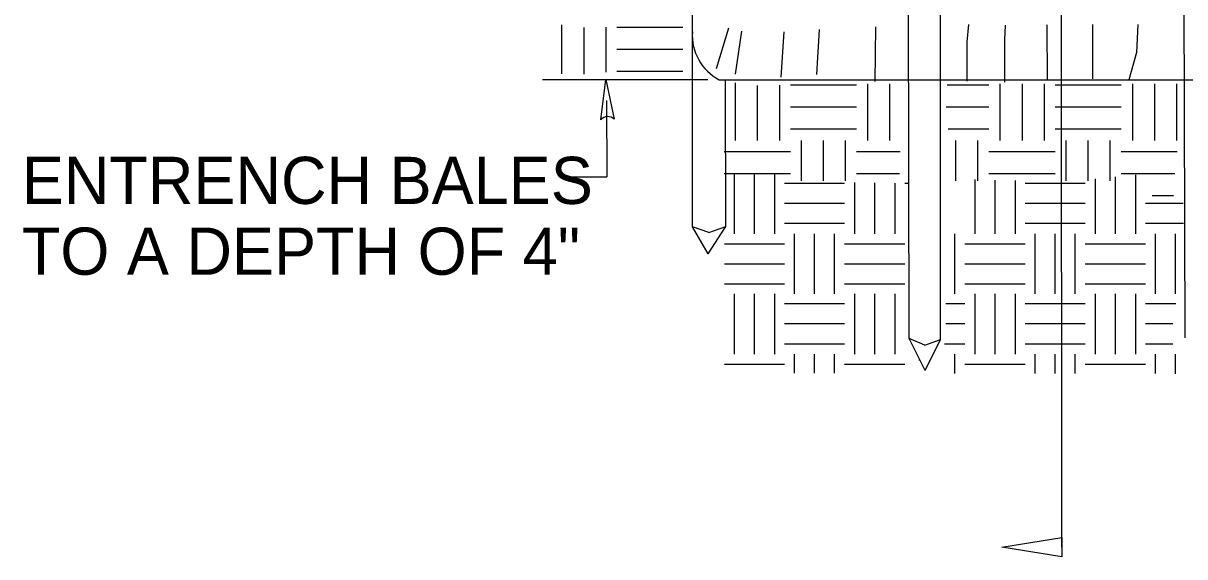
# Model space of a CAD drawing. Extents: x 0 to 2.83, y -0.06 to 1.83.
# Drawn here: x 0.5312 to 0.7467, y 0.8602 to 0.9591 of the extents above; entities that cross this region are included whole.
import ezdxf

# ---------------------------------------------------------------- set-up
doc = ezdxf.new("R2010")
doc.units = 0
for name, color, linetype in [('Edge_of_Truck_Apron', 7, 'Continuous'), ('Existing Soil', 7, 'Continuous'), ('Haybales', 7, 'Continuous'), ('Longitudinal Joint', 7, 'Continuous'), ('Wood Stakes', 7, 'Continuous')]:
    doc.layers.add(name, color=color, linetype=linetype)

msp = doc.modelspace()

# ---------------------------------------------------------------- linework, layer by layer
at = {"layer": 'Edge_of_Truck_Apron'}
for p, q in [((0.7239419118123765, 0.8619778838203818), (0.7236669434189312, 1.1529230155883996)), ((0.6383749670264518, 0.9412304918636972), (0.6392960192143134, 0.9487215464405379)), ((0.6383749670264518, 0.9412304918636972), (0.6392960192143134, 0.9487215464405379)), ((0.6392960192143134, 0.9487215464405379), (0.6408542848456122, 0.941336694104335)), ((0.6392960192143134, 0.9487215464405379), (0.6408542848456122, 0.941336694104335)), ((0.639452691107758, 0.9448351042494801), (0.6395039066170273, 0.9306306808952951)), ((0.6308424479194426, 0.9306402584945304), (0.6395039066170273, 0.9306306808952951))]:
    msp.add_line(p, q, dxfattribs=at)
msp.add_lwpolyline([(0.7239455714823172, 0.8601893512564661), (0.7127635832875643, 0.8619550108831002), (0.7239382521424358, 0.8637664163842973)], close=True, dxfattribs=at)
msp.add_arc((0.6396640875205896, 0.9401288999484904), 0.0016956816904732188, 45.42043531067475, 139.48512104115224, dxfattribs=at)
msp.add_arc((0.6396640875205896, 0.9401288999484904), 0.0016956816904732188, 45.42043531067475, 139.48512104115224, dxfattribs=at)
at = {"layer": 'Existing Soil'}
for p, q in [((0.6310945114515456, 0.9588487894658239), (0.6310945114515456, 0.949758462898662)), ((0.6351891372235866, 0.9583418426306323), (0.6351891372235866, 0.9497080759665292)), ((0.6392837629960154, 0.9584000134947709), (0.6392837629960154, 0.9500607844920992)), ((0.6536149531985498, 0.9583877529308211), (0.6413310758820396, 0.9583877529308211)), ((0.6536149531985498, 0.954293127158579), (0.6413310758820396, 0.954293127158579)), ((0.6536149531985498, 0.9501985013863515), (0.6413310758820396, 0.9501985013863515)), ((0.6633135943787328, 0.9481212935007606), (0.6633135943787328, 0.9374236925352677)), ((0.6633135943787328, 0.9481212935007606), (0.6633135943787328, 0.9374236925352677)), ((0.6674082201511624, 0.9476143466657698), (0.6674082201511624, 0.9374236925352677)), ((0.6674082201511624, 0.9476143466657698), (0.6674082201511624, 0.9374236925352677)), ((0.671502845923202, 0.9476725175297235), (0.671502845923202, 0.9374236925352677)), ((0.671502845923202, 0.9476725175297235), (0.671502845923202, 0.9374236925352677)), ((0.6858340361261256, 0.9476602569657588), (0.6735501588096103, 0.9476602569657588)), ((0.6858340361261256, 0.9476602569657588), (0.6735501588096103, 0.9476602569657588)), ((0.6878813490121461, 0.9478773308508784), (0.6878813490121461, 0.9374236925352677)), ((0.6878813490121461, 0.9478773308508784), (0.6878813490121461, 0.9374236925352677)), ((0.6919759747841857, 0.9478773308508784), (0.6919759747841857, 0.9374236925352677)), ((0.6919759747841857, 0.9478773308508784), (0.6919759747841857, 0.9374236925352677)), ((0.7104017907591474, 0.9476602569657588), (0.702675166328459, 0.9476602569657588)), ((0.7104017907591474, 0.9476602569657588), (0.702675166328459, 0.9476602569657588)), ((0.7124491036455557, 0.9478773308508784), (0.7124491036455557, 0.9374236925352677)), ((0.7124491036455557, 0.9478773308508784), (0.7124491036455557, 0.9374236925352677)), ((0.7165437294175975, 0.9478773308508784), (0.7165437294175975, 0.9374236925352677)), ((0.7165437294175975, 0.9478773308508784), (0.7165437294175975, 0.9374236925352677)), ((0.7206383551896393, 0.9478773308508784), (0.7206383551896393, 0.9374236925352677)), ((0.7206383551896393, 0.9478773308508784), (0.7206383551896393, 0.9374236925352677)), ((0.7349695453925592, 0.9476602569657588), (0.7226856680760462, 0.9476602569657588)), ((0.7349695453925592, 0.9476602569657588), (0.7226856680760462, 0.9476602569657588)), ((0.7370168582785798, 0.9478773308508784), (0.7370168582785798, 0.9374236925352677)), ((0.7370168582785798, 0.9478773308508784), (0.7370168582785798, 0.9374236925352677)), ((0.7411114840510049, 0.9478773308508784), (0.7411114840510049, 0.9374236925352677)), ((0.7411114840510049, 0.9478773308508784), (0.7411114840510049, 0.9374236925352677)), ((0.7452061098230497, 0.9478773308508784), (0.7452061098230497, 0.9374236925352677)), ((0.7452061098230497, 0.9478773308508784), (0.7452061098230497, 0.9374236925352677)), ((0.6858340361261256, 0.9435656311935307), (0.6735501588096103, 0.9435656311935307)), ((0.6858340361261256, 0.9435656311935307), (0.6735501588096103, 0.9435656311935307)), ((0.7104017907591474, 0.9435656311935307), (0.7024463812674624, 0.9435656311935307)), ((0.7104017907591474, 0.9435656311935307), (0.7024463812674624, 0.9435656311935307)), ((0.7349695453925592, 0.9435656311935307), (0.7226856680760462, 0.9435656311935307)), ((0.7349695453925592, 0.9435656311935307), (0.7226856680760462, 0.9435656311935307)), ((0.6858340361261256, 0.9394710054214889), (0.6735501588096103, 0.9394710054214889)), ((0.6858340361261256, 0.9394710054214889), (0.6735501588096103, 0.9394710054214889)), ((0.7104017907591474, 0.9394710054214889), (0.7028276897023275, 0.9394710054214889)), ((0.7104017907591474, 0.9394710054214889), (0.7028276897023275, 0.9394710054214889)), ((0.7349695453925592, 0.9394710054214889), (0.7226856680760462, 0.9394710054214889)), ((0.7349695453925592, 0.9394710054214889), (0.7226856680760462, 0.9394710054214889)), ((0.6755974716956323, 0.9299010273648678), (0.6755974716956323, 0.9374236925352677)), ((0.6755974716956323, 0.9299010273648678), (0.6755974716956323, 0.9374236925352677)), ((0.6796920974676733, 0.9299010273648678), (0.6796920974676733, 0.9374236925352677)), ((0.6796920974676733, 0.9299010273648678), (0.6796920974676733, 0.9374236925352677)), ((0.6837867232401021, 0.9299010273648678), (0.6837867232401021, 0.9374236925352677)), ((0.6837867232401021, 0.9299010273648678), (0.6837867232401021, 0.9374236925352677)), ((0.704259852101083, 0.9299010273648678), (0.704259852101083, 0.9374236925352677)), ((0.704259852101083, 0.9299010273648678), (0.704259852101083, 0.9374236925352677)), ((0.708354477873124, 0.9299010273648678), (0.708354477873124, 0.9374236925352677)), ((0.708354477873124, 0.9299010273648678), (0.708354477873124, 0.9374236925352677)), ((0.7247329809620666, 0.9299010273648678), (0.7247329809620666, 0.9374236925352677)), ((0.7247329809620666, 0.9299010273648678), (0.7247329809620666, 0.9374236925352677)), ((0.7288276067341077, 0.9299010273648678), (0.7288276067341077, 0.9374236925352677)), ((0.7288276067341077, 0.9299010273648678), (0.7288276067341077, 0.9374236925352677)), ((0.7329222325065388, 0.9299010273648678), (0.7329222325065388, 0.9374236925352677)), ((0.7329222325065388, 0.9299010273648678), (0.7329222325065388, 0.9374236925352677)), ((0.6858340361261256, 0.935376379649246), (0.6939050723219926, 0.935376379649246)), ((0.6858340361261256, 0.935376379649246), (0.6939050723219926, 0.935376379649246)), ((0.7104017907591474, 0.935376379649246), (0.7226856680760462, 0.935376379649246)), ((0.7104017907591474, 0.935376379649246), (0.7226856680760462, 0.935376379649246)), ((0.7349695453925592, 0.935376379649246), (0.7453067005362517, 0.935376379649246)), ((0.7349695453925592, 0.935376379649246), (0.7453067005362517, 0.935376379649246)), ((0.6858340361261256, 0.931281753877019), (0.6938288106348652, 0.931281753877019)), ((0.6858340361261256, 0.931281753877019), (0.6938288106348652, 0.931281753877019)), ((0.7104017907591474, 0.931281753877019), (0.7226856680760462, 0.931281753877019)), ((0.7104017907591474, 0.931281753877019), (0.7226856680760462, 0.931281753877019)), ((0.7349695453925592, 0.931281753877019), (0.7448796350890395, 0.931281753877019)), ((0.7349695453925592, 0.931281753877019), (0.7448796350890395, 0.931281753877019)), ((0.6631274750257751, 0.9312783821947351), (0.6631274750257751, 0.9201145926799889)), ((0.6631274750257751, 0.9312783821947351), (0.6631274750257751, 0.9201145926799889)), ((0.6668498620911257, 0.9312716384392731), (0.6668498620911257, 0.9201145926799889)), ((0.6668498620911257, 0.9312716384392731), (0.6668498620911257, 0.9201145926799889)), ((0.6705722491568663, 0.9312648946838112), (0.6705722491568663, 0.9201145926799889)), ((0.6705722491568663, 0.9312648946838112), (0.6705722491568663, 0.9201145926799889)), ((0.6836006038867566, 0.9294205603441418), (0.6724334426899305, 0.9294205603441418)), ((0.6836006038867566, 0.9294205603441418), (0.6724334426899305, 0.9294205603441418)), ((0.685461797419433, 0.9296342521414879), (0.685461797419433, 0.9201145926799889)), ((0.685461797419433, 0.9296342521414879), (0.685461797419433, 0.9201145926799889)), ((0.6891841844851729, 0.9295539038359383), (0.6891841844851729, 0.9201145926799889)), ((0.6891841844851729, 0.9295539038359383), (0.6891841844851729, 0.9201145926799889)), ((0.6929065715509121, 0.9294735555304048), (0.6929065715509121, 0.9201145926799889)), ((0.6929065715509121, 0.9294735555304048), (0.6929065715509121, 0.9201145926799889)), ((0.6953617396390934, 0.9294205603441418), (0.6947677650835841, 0.9294205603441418)), ((0.6953617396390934, 0.9294205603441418), (0.6947677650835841, 0.9294205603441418)), ((0.707796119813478, 0.9301386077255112), (0.707796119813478, 0.9201145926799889)), ((0.707796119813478, 0.9301386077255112), (0.707796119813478, 0.9201145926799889)), ((0.7115185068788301, 0.9300602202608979), (0.7115185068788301, 0.9201145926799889)), ((0.7115185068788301, 0.9300602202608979), (0.7115185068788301, 0.9201145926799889)), ((0.71524089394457, 0.9299818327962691), (0.71524089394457, 0.9201145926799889)), ((0.71524089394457, 0.9299818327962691), (0.71524089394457, 0.9201145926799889)), ((0.7282692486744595, 0.9294205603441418), (0.7171020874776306, 0.9294205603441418)), ((0.7282692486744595, 0.9294205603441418), (0.7171020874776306, 0.9294205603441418)), ((0.7301304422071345, 0.930299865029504), (0.7301304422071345, 0.9201145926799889)), ((0.7301304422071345, 0.930299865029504), (0.7301304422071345, 0.9201145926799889)), ((0.7338528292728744, 0.9306669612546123), (0.7338528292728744, 0.9201145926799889)), ((0.7338528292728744, 0.9306669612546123), (0.7338528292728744, 0.9201145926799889)), ((0.7375752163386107, 0.9310340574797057), (0.7375752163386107, 0.9201145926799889)), ((0.7375752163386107, 0.9310340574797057), (0.7375752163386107, 0.9201145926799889)), ((0.7407028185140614, 0.927187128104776), (0.7446355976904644, 0.927187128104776)), ((0.7407028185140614, 0.927187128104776), (0.7446355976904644, 0.927187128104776)), ((0.6836006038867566, 0.9256981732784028), (0.6724334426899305, 0.9256981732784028)), ((0.6836006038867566, 0.9256981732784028), (0.6724334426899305, 0.9256981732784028)), ((0.7282692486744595, 0.9256981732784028), (0.7171020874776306, 0.9256981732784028)), ((0.7282692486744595, 0.9256981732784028), (0.7171020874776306, 0.9256981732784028)), ((0.7464678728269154, 0.9256981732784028), (0.7394364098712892, 0.9256981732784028)), ((0.7464678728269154, 0.9256981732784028), (0.7394364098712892, 0.9256981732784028)), ((0.6836006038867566, 0.9219757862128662), (0.6724334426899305, 0.9219757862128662)), ((0.6836006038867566, 0.9219757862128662), (0.6724334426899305, 0.9219757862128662)), ((0.7282692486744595, 0.9219757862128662), (0.7171020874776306, 0.9219757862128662)), ((0.7282692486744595, 0.9219757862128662), (0.7171020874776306, 0.9219757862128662)), ((0.7465155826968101, 0.9219757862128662), (0.7394364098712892, 0.9219757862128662)), ((0.7465155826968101, 0.9219757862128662), (0.7394364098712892, 0.9219757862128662)), ((0.6742946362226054, 0.9089474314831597), (0.6742946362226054, 0.9201145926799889)), ((0.6742946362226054, 0.9089474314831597), (0.6742946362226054, 0.9201145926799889)), ((0.6780170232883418, 0.9089474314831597), (0.6780170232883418, 0.9201145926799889)), ((0.6780170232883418, 0.9089474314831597), (0.6780170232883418, 0.9201145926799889)), ((0.6817394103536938, 0.9089474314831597), (0.6817394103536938, 0.9201145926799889)), ((0.6817394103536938, 0.9089474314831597), (0.6817394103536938, 0.9201145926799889)), ((0.7040737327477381, 0.9089474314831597), (0.7040737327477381, 0.9201145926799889)), ((0.7040737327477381, 0.9089474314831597), (0.7040737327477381, 0.9201145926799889)), ((0.7189632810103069, 0.9089474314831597), (0.7189632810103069, 0.9201145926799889)), ((0.7189632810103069, 0.9089474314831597), (0.7189632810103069, 0.9201145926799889)), ((0.7226856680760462, 0.9089474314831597), (0.7226856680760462, 0.9201145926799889)), ((0.7226856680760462, 0.9089474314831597), (0.7226856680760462, 0.9201145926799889)), ((0.7264080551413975, 0.9089474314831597), (0.7264080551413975, 0.9201145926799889)), ((0.7264080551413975, 0.9089474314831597), (0.7264080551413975, 0.9201145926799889)), ((0.7412976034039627, 0.9089474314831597), (0.7412976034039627, 0.9201145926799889)), ((0.7412976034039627, 0.9089474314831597), (0.7412976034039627, 0.9201145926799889)), ((0.745019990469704, 0.9089474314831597), (0.745019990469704, 0.9201145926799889)), ((0.745019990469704, 0.9089474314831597), (0.745019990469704, 0.9201145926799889)), ((0.6836006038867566, 0.9182533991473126), (0.6947677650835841, 0.9182533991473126)), ((0.6836006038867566, 0.9182533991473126), (0.6947677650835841, 0.9182533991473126)), ((0.7059349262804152, 0.9182533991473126), (0.7171020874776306, 0.9182533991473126)), ((0.7059349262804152, 0.9182533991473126), (0.7171020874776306, 0.9182533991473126)), ((0.7282692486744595, 0.9182533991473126), (0.7394364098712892, 0.9182533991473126)), ((0.7282692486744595, 0.9182533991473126), (0.7394364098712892, 0.9182533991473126)), ((0.661304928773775, 0.9145310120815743), (0.6724334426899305, 0.9145310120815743)), ((0.661304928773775, 0.9145310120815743), (0.6724334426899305, 0.9145310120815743)), ((0.6836006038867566, 0.9145310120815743), (0.6947677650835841, 0.9145310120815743)), ((0.6836006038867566, 0.9145310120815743), (0.6947677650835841, 0.9145310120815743)), ((0.7059349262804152, 0.9145310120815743), (0.7171020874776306, 0.9145310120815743)), ((0.7059349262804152, 0.9145310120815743), (0.7171020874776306, 0.9145310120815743)), ((0.7282692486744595, 0.9145310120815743), (0.7394364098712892, 0.9145310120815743)), ((0.7282692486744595, 0.9145310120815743), (0.7394364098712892, 0.9145310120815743)), ((0.6613135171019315, 0.9108086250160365), (0.6724334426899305, 0.9108086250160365)), ((0.6613135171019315, 0.9108086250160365), (0.6724334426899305, 0.9108086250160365)), ((0.6836006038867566, 0.9108086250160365), (0.6947677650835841, 0.9108086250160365)), ((0.6836006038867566, 0.9108086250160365), (0.6947677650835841, 0.9108086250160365)), ((0.7059349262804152, 0.9108086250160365), (0.7171020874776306, 0.9108086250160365)), ((0.7059349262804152, 0.9108086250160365), (0.7171020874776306, 0.9108086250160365)), ((0.7282692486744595, 0.9108086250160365), (0.7394364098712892, 0.9108086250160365)), ((0.7282692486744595, 0.9108086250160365), (0.7394364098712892, 0.9108086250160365)), ((0.6631274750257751, 0.9089474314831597), (0.6631274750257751, 0.8977802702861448)), ((0.6631274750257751, 0.9089474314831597), (0.6631274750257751, 0.8977802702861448)), ((0.6668498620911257, 0.9089474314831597), (0.6668498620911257, 0.8977802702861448)), ((0.6668498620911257, 0.9089474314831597), (0.6668498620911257, 0.8977802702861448)), ((0.6705722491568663, 0.9089474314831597), (0.6705722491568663, 0.8977802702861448)), ((0.6705722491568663, 0.9089474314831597), (0.6705722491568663, 0.8977802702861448)), ((0.685461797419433, 0.9089474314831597), (0.685461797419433, 0.8977802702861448)), ((0.685461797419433, 0.9089474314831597), (0.685461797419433, 0.8977802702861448)), ((0.6891841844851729, 0.9089474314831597), (0.6891841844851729, 0.8977802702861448)), ((0.6891841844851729, 0.9089474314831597), (0.6891841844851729, 0.8977802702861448)), ((0.6929065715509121, 0.9089474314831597), (0.6929065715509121, 0.8977802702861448)), ((0.6929065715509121, 0.9089474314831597), (0.6929065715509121, 0.8977802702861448)), ((0.707796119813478, 0.9089474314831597), (0.707796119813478, 0.8977802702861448)), ((0.707796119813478, 0.9089474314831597), (0.707796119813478, 0.8977802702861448)), ((0.7115185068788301, 0.9089474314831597), (0.7115185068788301, 0.8977802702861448)), ((0.7115185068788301, 0.9089474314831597), (0.7115185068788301, 0.8977802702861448)), ((0.71524089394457, 0.9089474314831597), (0.71524089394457, 0.8977802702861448)), ((0.71524089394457, 0.9089474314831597), (0.71524089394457, 0.8977802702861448)), ((0.7301304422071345, 0.9089474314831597), (0.7301304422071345, 0.8977802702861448)), ((0.7301304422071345, 0.9089474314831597), (0.7301304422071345, 0.8977802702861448)), ((0.7338528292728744, 0.9089474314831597), (0.7338528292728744, 0.8977802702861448)), ((0.7338528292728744, 0.9089474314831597), (0.7338528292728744, 0.8977802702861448)), ((0.7375752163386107, 0.9089474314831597), (0.7375752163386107, 0.8977802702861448)), ((0.7375752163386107, 0.9089474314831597), (0.7375752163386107, 0.8977802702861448)), ((0.6836006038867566, 0.9070862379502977), (0.6724334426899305, 0.9070862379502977)), ((0.6836006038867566, 0.9070862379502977), (0.6724334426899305, 0.9070862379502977)), ((0.7059349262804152, 0.9070862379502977), (0.7024157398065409, 0.9070862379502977)), ((0.7059349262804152, 0.9070862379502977), (0.7024157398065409, 0.9070862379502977)), ((0.7282692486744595, 0.9070862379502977), (0.7171020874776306, 0.9070862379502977)), ((0.7282692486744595, 0.9070862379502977), (0.7171020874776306, 0.9070862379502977)), ((0.7451141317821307, 0.9070862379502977), (0.7394364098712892, 0.9070862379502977)), ((0.7451141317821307, 0.9070862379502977), (0.7394364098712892, 0.9070862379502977)), ((0.6836006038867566, 0.9033638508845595), (0.6724334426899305, 0.9033638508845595)), ((0.6836006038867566, 0.9033638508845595), (0.6724334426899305, 0.9033638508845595)), ((0.7059349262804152, 0.9033638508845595), (0.7024157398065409, 0.9033638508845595)), ((0.7059349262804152, 0.9033638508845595), (0.7024157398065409, 0.9033638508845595)), ((0.7282692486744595, 0.9033638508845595), (0.7171020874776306, 0.9033638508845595)), ((0.7282692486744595, 0.9033638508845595), (0.7171020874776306, 0.9033638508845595)), ((0.7445421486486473, 0.9033638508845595), (0.7394364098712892, 0.9033638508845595)), ((0.7445421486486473, 0.9033638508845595), (0.7394364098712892, 0.9033638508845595)), ((0.6836006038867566, 0.8996414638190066), (0.6724334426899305, 0.8996414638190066)), ((0.6836006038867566, 0.8996414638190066), (0.6724334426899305, 0.8996414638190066)), ((0.7059349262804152, 0.8996414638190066), (0.7021774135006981, 0.8996414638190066)), ((0.7059349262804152, 0.8996414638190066), (0.7021774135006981, 0.8996414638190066)), ((0.7282692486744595, 0.8996414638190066), (0.7171020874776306, 0.8996414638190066)), ((0.7282692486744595, 0.8996414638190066), (0.7171020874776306, 0.8996414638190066)), ((0.7445421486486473, 0.8996414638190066), (0.7394364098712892, 0.8996414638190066)), ((0.7445421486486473, 0.8996414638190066), (0.7394364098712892, 0.8996414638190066)), ((0.6742946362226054, 0.8942439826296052), (0.6742946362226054, 0.8977802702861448)), ((0.6742946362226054, 0.8942439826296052), (0.6742946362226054, 0.8977802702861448)), ((0.6780170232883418, 0.8942389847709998), (0.6780170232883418, 0.8977802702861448)), ((0.6780170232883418, 0.8942389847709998), (0.6780170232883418, 0.8977802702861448)), ((0.6817394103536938, 0.8942339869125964), (0.6817394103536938, 0.8977802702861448)), ((0.6817394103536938, 0.8942339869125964), (0.6817394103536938, 0.8977802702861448)), ((0.7040737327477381, 0.8942039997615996), (0.7040737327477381, 0.8977802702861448)), ((0.7040737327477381, 0.8942039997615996), (0.7040737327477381, 0.8977802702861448)), ((0.7189632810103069, 0.8941840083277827), (0.7189632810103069, 0.8977802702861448)), ((0.7189632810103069, 0.8941840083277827), (0.7189632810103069, 0.8977802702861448)), ((0.7226856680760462, 0.8941790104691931), (0.7226856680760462, 0.8977802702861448)), ((0.7226856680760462, 0.8941790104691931), (0.7226856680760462, 0.8977802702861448)), ((0.7264080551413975, 0.8941740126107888), (0.7264080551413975, 0.8977802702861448)), ((0.7264080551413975, 0.8941740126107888), (0.7264080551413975, 0.8977802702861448)), ((0.7412976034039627, 0.8941540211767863), (0.7412976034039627, 0.8977802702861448)), ((0.7412976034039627, 0.8941540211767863), (0.7412976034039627, 0.8977802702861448)), ((0.745019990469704, 0.8941490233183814), (0.745019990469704, 0.8977802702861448)), ((0.745019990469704, 0.8941490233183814), (0.745019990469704, 0.8977802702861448)), ((0.6613478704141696, 0.8959190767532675), (0.6724334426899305, 0.8959190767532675)), ((0.6613478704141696, 0.8959190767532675), (0.6724334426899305, 0.8959190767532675)), ((0.6836006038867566, 0.8959190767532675), (0.6947677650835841, 0.8959190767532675)), ((0.6836006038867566, 0.8959190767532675), (0.6947677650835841, 0.8959190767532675)), ((0.7059349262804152, 0.8959190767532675), (0.7171020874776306, 0.8959190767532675)), ((0.7059349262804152, 0.8959190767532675), (0.7171020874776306, 0.8959190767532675)), ((0.7282692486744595, 0.8959190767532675), (0.7394364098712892, 0.8959190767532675)), ((0.7282692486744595, 0.8959190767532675), (0.7394364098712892, 0.8959190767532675))]:
    msp.add_line(p, q, dxfattribs=at)
at = {"layer": 'Haybales'}
for p, q in [((0.6553708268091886, 0.9575566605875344), (0.6552817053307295, 1.0384090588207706)), ((0.6553708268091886, 0.9575566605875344), (0.6552817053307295, 1.0384090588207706)), ((0.6598220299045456, 0.9507249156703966), (0.6621550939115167, 0.9582975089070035)), ((0.6598220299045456, 0.9507249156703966), (0.6621550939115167, 0.9582975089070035)), ((0.6645069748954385, 0.9576722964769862), (0.6633120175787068, 0.9497036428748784)), ((0.6645069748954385, 0.9576722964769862), (0.6633120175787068, 0.9497036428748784)), ((0.6723050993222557, 0.957539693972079), (0.6717981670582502, 0.9491730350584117)), ((0.6723050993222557, 0.957539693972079), (0.6717981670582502, 0.9491730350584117)), ((0.678899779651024, 0.9579906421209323), (0.6783928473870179, 0.9496239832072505)), ((0.678899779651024, 0.9579906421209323), (0.6783928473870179, 0.9496239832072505)), ((0.6892918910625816, 0.9483563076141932), (0.6894320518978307, 0.9584918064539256)), ((0.6892918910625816, 0.9483563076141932), (0.6894320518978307, 0.9584918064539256)), ((0.7066291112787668, 0.9589142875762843), (0.70628923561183, 0.9556845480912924)), ((0.7066291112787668, 0.9589142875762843), (0.70628923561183, 0.9556845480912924)), ((0.7134197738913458, 0.9587692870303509), (0.7132706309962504, 0.9560093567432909)), ((0.7134197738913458, 0.9587692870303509), (0.7132706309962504, 0.9560093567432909)), ((0.7211472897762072, 0.9588362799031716), (0.7211926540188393, 0.9485982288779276)), ((0.7211472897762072, 0.9588362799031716), (0.7211926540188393, 0.9485982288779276)), ((0.7296317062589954, 0.9589316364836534), (0.7296317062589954, 0.9488270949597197)), ((0.7296317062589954, 0.9589316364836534), (0.7296317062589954, 0.9488270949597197)), ((0.7380093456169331, 0.9589075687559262), (0.737773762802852, 0.9537233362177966)), ((0.7380093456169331, 0.9589075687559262), (0.737773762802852, 0.9537233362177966)), ((0.70628923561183, 0.9556845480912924), (0.70628923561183, 0.9483763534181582)), ((0.70628923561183, 0.9556845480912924), (0.70628923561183, 0.9483763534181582)), ((0.737773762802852, 0.9537233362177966), (0.7363543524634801, 0.9486526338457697)), ((0.737773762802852, 0.9537233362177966), (0.7363543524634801, 0.9486526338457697)), ((0.6603424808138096, 0.948676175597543), (0.8055369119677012, 0.948676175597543)), ((0.6603424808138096, 0.948676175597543), (0.8055369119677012, 0.948676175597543))]:
    msp.add_line(p, q, dxfattribs=at)
msp.add_arc((0.6646313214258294, 0.9569091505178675), 0.009283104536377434, 176.00028812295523, 242.48343833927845, dxfattribs=at)
msp.add_arc((0.6646313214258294, 0.9569091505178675), 0.009283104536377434, 176.00028812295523, 242.48343833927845, dxfattribs=at)
at = {"layer": 'Longitudinal Joint'}
for p, q in [((0.7014009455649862, 0.9006230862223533), (0.7014238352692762, 0.9873487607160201)), ((0.6310945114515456, 0.9588487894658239), (0.6310945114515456, 0.949758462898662)), ((0.6351891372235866, 0.9583418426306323), (0.6351891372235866, 0.9497080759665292)), ((0.6392837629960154, 0.9584000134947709), (0.6392837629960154, 0.9500607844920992)), ((0.6536149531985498, 0.9583877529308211), (0.6413310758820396, 0.9583877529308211)), ((0.6553899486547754, 0.9213868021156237), (0.6553708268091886, 0.9575566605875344)), ((0.7132706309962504, 0.9560093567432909), (0.7132706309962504, 0.9482139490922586)), ((0.7132706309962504, 0.9560093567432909), (0.7132706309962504, 0.9482139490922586)), ((0.6536149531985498, 0.954293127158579), (0.6413310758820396, 0.954293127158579)), ((0.6582508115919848, 0.9486756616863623), (0.6275373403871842, 0.9486681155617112)), ((0.6582508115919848, 0.9486756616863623), (0.6275373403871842, 0.9486681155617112)), ((0.6536149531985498, 0.9501985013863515), (0.6413310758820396, 0.9501985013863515)), ((0.6615679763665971, 0.921443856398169), (0.6614911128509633, 0.9485766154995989)), ((0.639452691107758, 0.9448351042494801), (0.6395039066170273, 0.9306306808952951)), ((0.6612662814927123, 0.935376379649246), (0.6735501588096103, 0.935376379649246)), ((0.6612662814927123, 0.935376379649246), (0.6735501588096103, 0.935376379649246)), ((0.6612662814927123, 0.931281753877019), (0.6735501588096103, 0.931281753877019)), ((0.6612662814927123, 0.931281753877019), (0.6735501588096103, 0.931281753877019)), ((0.6308424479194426, 0.9306402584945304), (0.6395039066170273, 0.9306306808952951)), ((0.6582972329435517, 0.9163564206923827), (0.6553899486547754, 0.9213868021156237)), ((0.6584027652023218, 0.9203492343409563), (0.6553899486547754, 0.9213868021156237)), ((0.6582972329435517, 0.9163564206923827), (0.6615679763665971, 0.921443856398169)), ((0.6584027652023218, 0.9203492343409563), (0.6615679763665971, 0.921443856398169)), ((0.6612963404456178, 0.9182533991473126), (0.6724334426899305, 0.9182533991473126)), ((0.6612963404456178, 0.9182533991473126), (0.6724334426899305, 0.9182533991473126)), ((0.6985393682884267, 0.8947343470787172), (0.695585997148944, 0.9006696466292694)), ((0.6984915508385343, 0.8994140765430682), (0.695585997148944, 0.9006696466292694)), ((0.6984915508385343, 0.8994140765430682), (0.7014075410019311, 0.9005143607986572)), ((0.6985393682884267, 0.8947343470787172), (0.7014075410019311, 0.9005143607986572)), ((0.6975756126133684, 0.8966711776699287), (0.6973910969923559, 0.8966711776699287)), ((0.6975756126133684, 0.8966711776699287), (0.6973910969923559, 0.8966711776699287))]:
    msp.add_line(p, q, dxfattribs=at)
at = {"layer": 'Wood Stakes'}
for p, q in [((0.7014075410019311, 0.9005143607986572), (0.7014238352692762, 0.9873487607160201)), ((0.695585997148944, 0.9006696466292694), (0.6954195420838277, 0.9757475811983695)), ((0.7467912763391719, 0.900822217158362), (0.7466248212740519, 0.9757475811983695)), ((0.6553899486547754, 0.9213868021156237), (0.6553708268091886, 0.9575566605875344)), ((0.6615679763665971, 0.921443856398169), (0.6614911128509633, 0.9485766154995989)), ((0.6582972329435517, 0.9163564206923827), (0.6553899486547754, 0.9213868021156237)), ((0.6584027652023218, 0.9203492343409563), (0.6553899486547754, 0.9213868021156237)), ((0.6582972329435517, 0.9163564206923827), (0.6615679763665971, 0.921443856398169)), ((0.6584027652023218, 0.9203492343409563), (0.6615679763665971, 0.921443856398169)), ((0.6985393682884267, 0.8947343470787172), (0.695585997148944, 0.9006696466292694)), ((0.6984915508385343, 0.8994140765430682), (0.695585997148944, 0.9006696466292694)), ((0.6984915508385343, 0.8994140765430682), (0.7014075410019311, 0.9005143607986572)), ((0.6985393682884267, 0.8947343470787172), (0.7014075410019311, 0.9005143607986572))]:
    msp.add_line(p, q, dxfattribs=at)

# ---------------------------------------------------------------- texts
at = {"layer": 'Edge_of_Truck_Apron'}
for s, p in [('ENTRENCH BALES ', (0.530909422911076, 0.9256250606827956)), ('TO A DEPTH OF 4"', (0.530909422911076, 0.9125000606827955))]:
    msp.add_text(s, height=0.008749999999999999, dxfattribs=at).set_placement(p)

doc.saveas('drawing.dxf')
